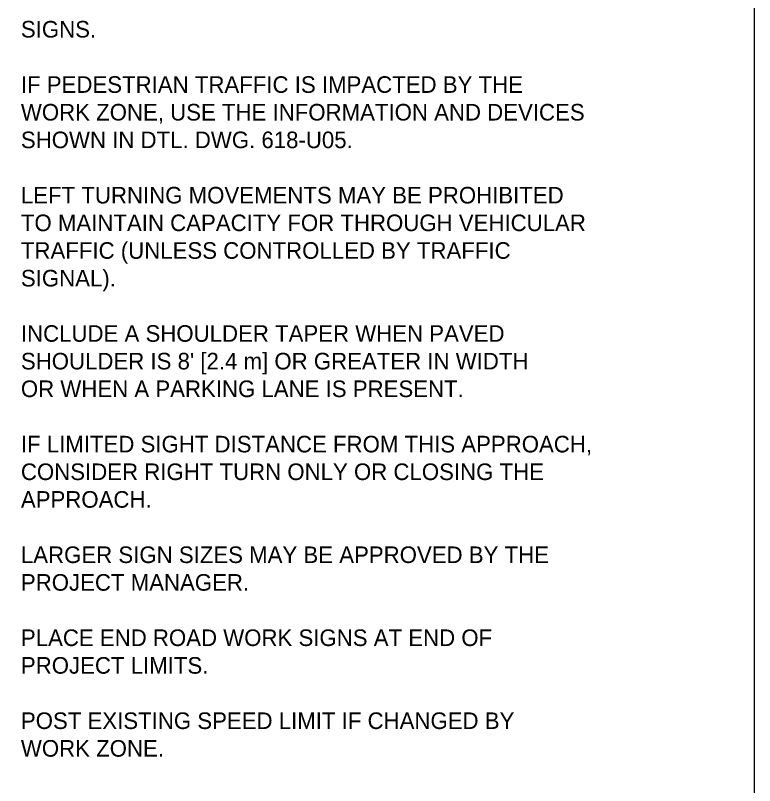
# Model space of a CAD drawing. Extents: x 49991.4 to 50021, y 49987.6 to 50011.4.
# Drawn here: x 50005.943 to 50008.615, y 50005.542 to 50008.327 of the extents above; entities that cross this region are included whole.
import ezdxf

# ---------------------------------------------------------------- set-up
doc = ezdxf.new("R2010")
doc.units = 0
doc.layers.add('Level 1', color=7, linetype='Continuous')
doc.layers.add('Level 2', color=7, linetype='Continuous')

msp = doc.modelspace()

# ---------------------------------------------------------------- linework, layer by layer
at = {"layer": 'Level 1'}
msp.add_lwpolyline([(50008.6146, 50011.2628), (50000.3356, 50011.2628), (50000.3356, 50000.0624), (50008.6146, 50000.0624)], close=True, dxfattribs=at)

# ---------------------------------------------------------------- texts
at = {"layer": 'Level 2'}
for s, p in [('SIGNS.', (50005.9633, 50008.2467)), ('IF PEDESTRIAN TRAFFIC IS IMPACTED BY THE', (50005.9633, 50008.0467)), ('WORK ZONE, USE THE INFORMATION AND DEVICES', (50005.9633, 50007.9467)), ('SHOWN IN DTL. DWG. 618-U05.', (50005.9633, 50007.8467)), ('LEFT TURNING MOVEMENTS MAY BE PROHIBITED', (50005.9633, 50007.6467)), ('TO MAINTAIN CAPACITY FOR THROUGH VEHICULAR', (50005.9633, 50007.5467)), ('TRAFFIC (UNLESS CONTROLLED BY TRAFFIC', (50005.9633, 50007.4467)), ('SIGNAL).', (50005.9633, 50007.3467)), ('INCLUDE A SHOULDER TAPER WHEN PAVED', (50005.9633, 50007.1467)), ("SHOULDER IS 8' [2.4 m] OR GREATER IN WIDTH", (50005.9633, 50007.0467)), ('OR WHEN A PARKING LANE IS PRESENT.', (50005.9633, 50006.9467)), ('IF LIMITED SIGHT DISTANCE FROM THIS APPROACH,', (50005.9633, 50006.7467)), ('CONSIDER RIGHT TURN ONLY OR CLOSING THE ', (50005.9633, 50006.6467)), ('APPROACH.', (50005.9633, 50006.5467)), ('LARGER SIGN SIZES MAY BE APPROVED BY THE ', (50005.9633, 50006.3467)), ('PROJECT MANAGER.', (50005.9633, 50006.2467)), ('PLACE END ROAD WORK SIGNS AT END OF', (50005.9633, 50006.0467)), ('PROJECT LIMITS.', (50005.9633, 50005.9467)), ('POST EXISTING SPEED LIMIT IF CHANGED BY', (50005.9633, 50005.7467)), ('WORK ZONE.', (50005.9633, 50005.6467))]:
    msp.add_text(s, height=0.06, dxfattribs=at).set_placement(p)

doc.saveas('drawing.dxf')
